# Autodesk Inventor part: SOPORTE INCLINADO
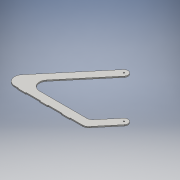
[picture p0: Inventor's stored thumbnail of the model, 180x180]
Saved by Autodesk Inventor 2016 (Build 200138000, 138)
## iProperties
Created: 2016-06
Part Number: SOPORTE INCLINADO
Material: Genérico
Document SubType Name: Modeling
Designer: adm
Density: 1 g/cm^3
Appearance: Valor por defecto
Author: adm
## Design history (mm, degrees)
sketch "Boceto1"
  geometry: L1 (75.83, -250.705)-(156.742, -154.277); L2 (57.177, -210.705)-(126.1, -128.566); L3 (34.196, -221.421)-(-203.95, -221.421); L4 (-54.102, 59.39)-(-234.592, -155.71); L5 (-86.032, 83.566)-(-320.372, -195.71); L6 (-269.73, -261.421)-(-269.73, -264.421); L7 (-229.73, -261.421)-(-229.73, -264.421); L8 (-159.73, -261.421)-(-159.73, -264.421); L9 (-119.73, -261.421)-(-119.73, -264.421); L10 (-49.73, -261.421)-(-49.73, -264.421); L11 (-9.73, -261.421)-(-9.73, -264.421); L12 (-49.73, -264.421)-(-9.73, -264.421); L13 (-269.73, -264.421)-(-229.73, -264.421); L14 (-159.73, -264.421)-(-119.73, -264.421); L15 (52.848, -261.421)-(-9.73, -261.421); L16 (-49.73, -261.421)-(-119.73, -261.421); L17 (-159.73, -261.421)-(-229.73, -261.421); L18 (-269.73, -261.421)-(-289.73, -261.421); C1 r 3.25 at (141.421, -141.421); C2 r 3.25 at (-70.711, 70.711); A1 r 30 centre (52.848, -231.421) between (52.848, -261.421) and (75.83, -250.705); A2 r 20 centre (141.421, -141.421) between (156.742, -154.277) and (126.1, -128.566); A3 r 30 centre (34.196, -191.421) between (34.196, -221.421) and (57.177, -210.705); A4 r 20.1 centre (-70.711, 70.711) between (-56.678, 56.32) and (-87.319, 82.032); A5 r 40 centre (-203.95, -181.421) between (-234.592, -155.71) and (-203.95, -221.421); A6 r 40 centre (-289.73, -221.421) between (-320.372, -195.71) and (-289.73, -261.421); 3 further points
  constraints: 36 end point, 15 tangent, 13 point on circle, 8 centre point, 2 coincident, 2 point on line
  dimensions: "d3" = 40 radius of A6; "d5" = 40 radius of A5; "d6" = 30 radius of A3; "d7" = 30 radius of A1; "d20" = 6.5 diameter of C2; "d21" = 6.5 diameter of C1
extrude "Extrusión1" new body sketch "Boceto1" distance "d18" = 6; taper "d19" = 0 deg
node "Sólido1"
other parameters: "d4" = 50 deg, "d11" = 3, "d23" = 3, "d33" = 3, "d34" = 2
